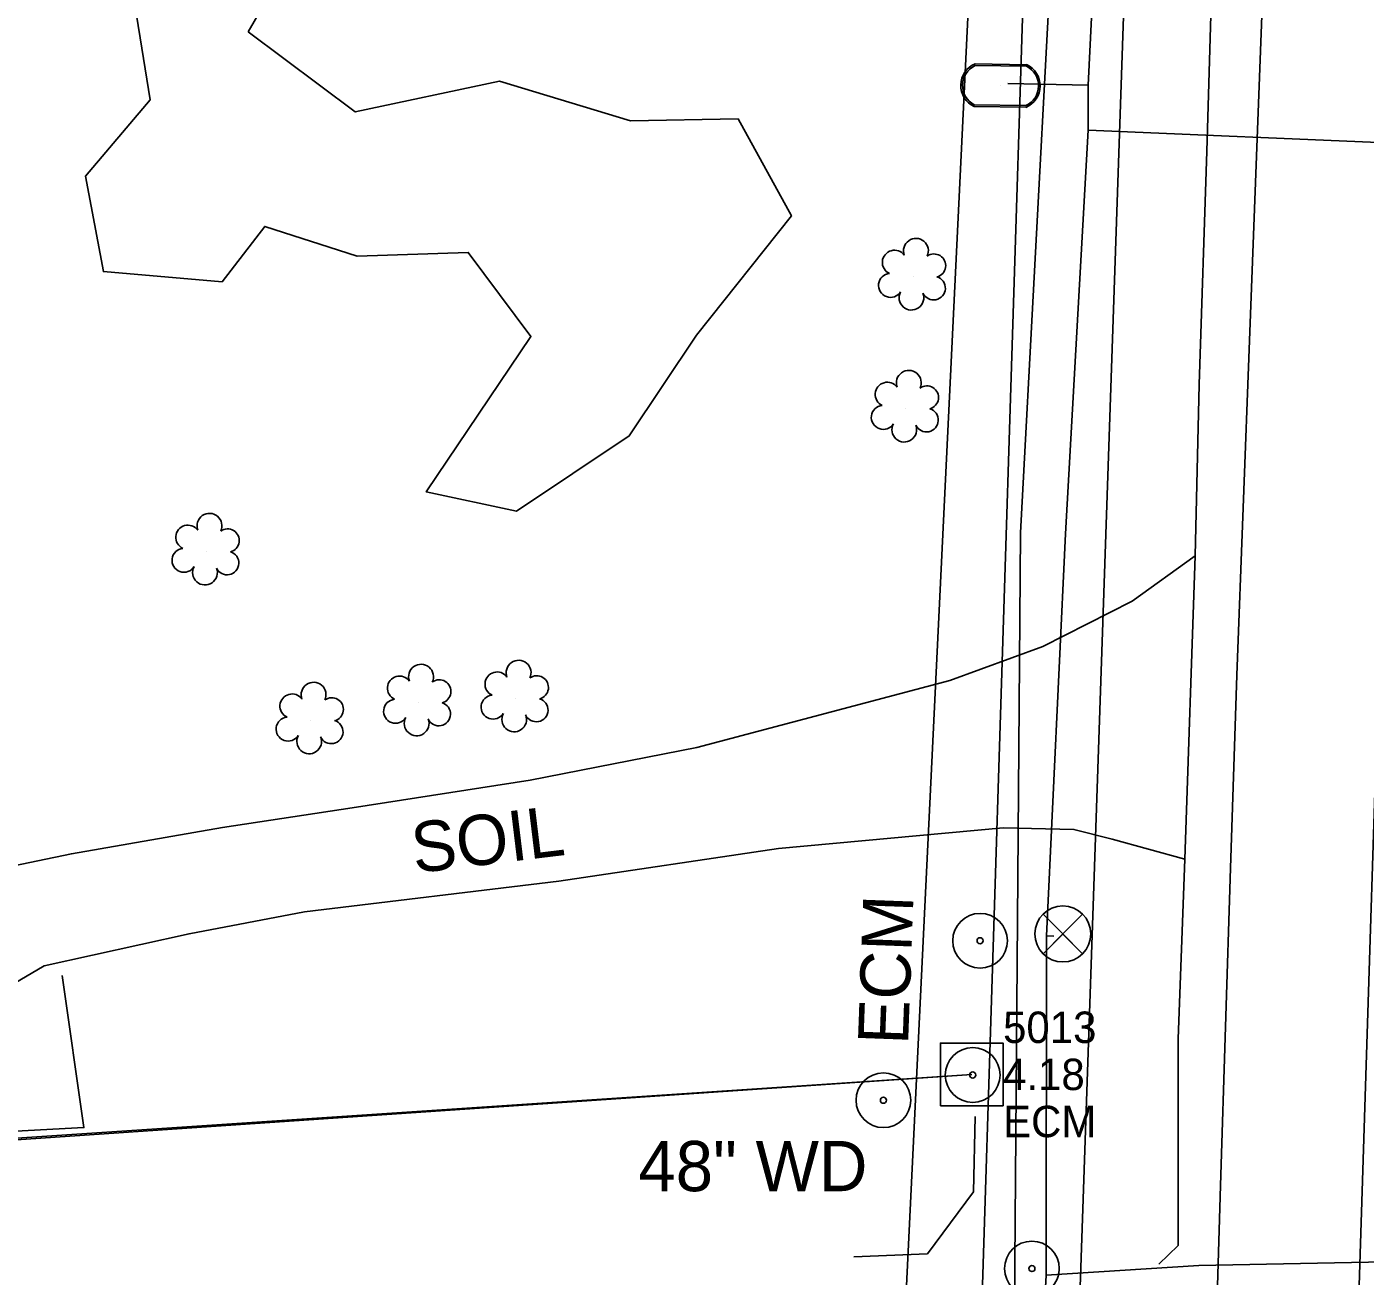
# Model space of a CAD drawing. Extents: x 3040896 to 3051146, y 687568 to 732976.
# Drawn here: x 3049720.6 to 3049827.2, y 689562.2 to 689661.6 of the extents above; entities that cross this region are included whole.
import ezdxf

# ---------------------------------------------------------------- set-up
doc = ezdxf.new("R2010")
doc.units = 0
for name, color, linetype in [('Exist Horizontal Alignment', 7, 'Continuous'), ('Exist Other Culture Fence Line', 7, 'Continuous'), ('Exist Other Culture Fence Line Text', 7, 'Continuous'), ('Exist Other Culture Located Object CELL', 7, 'Continuous'), ('Exist Property Line', 7, 'Continuous'), ('Exist Property Monument CELL', 7, 'Continuous'), ('Exist Property Monument Cogo Comment', 7, 'Continuous'), ('Exist Property Monument Cogo Elevation', 7, 'Continuous'), ('Exist Property Monument Cogo Number', 7, 'Continuous'), ('Exist Property Monument Text', 7, 'Continuous'), ('Exist Right of Way Line', 7, 'Continuous'), ('Exist Roads Change in Surface', 7, 'Continuous'), ('Exist Roads EOP', 7, 'Continuous'), ('Exist Roads EOT', 7, 'Continuous'), ('Exist Roads Soil', 7, 'Continuous'), ('Exist Roads Soil Text', 7, 'Continuous'), ('Exist Utilities Telephone UG Cable', 7, 'Continuous'), ('Exist Utilities Water Meter CELL', 7, 'Continuous'), ('Exist Utilities Water UG Line SUE', 7, 'Continuous'), ('Exist Utilities Water Valve CELL', 7, 'Continuous'), ('Exist Vegetation Shrub CELL', 7, 'Continuous'), ('Exist Vegetation Woods Line', 7, 'Continuous')]:
    doc.layers.add(name, color=color, linetype=linetype)

# ---------------------------------------------------------------- blocks, each defined once
blk = doc.blocks.new('EXIST PROPERTY MONUMENT')
at = {"layer": 'Exist Property Monument CELL'}
blk.add_line((0, 0), (0, 0), dxfattribs=at)
blk.add_lwpolyline([(-0.0499, -0.0499), (-0.0499, 0.0499), (0.0499, 0.0499), (0.0499, -0.0499), (-0.0499, -0.0499)], dxfattribs=at)

msp = doc.modelspace()

# ---------------------------------------------------------------- linework, layer by layer
at = {"layer": 'Exist Horizontal Alignment'}
msp.add_line((3049785.41, 688254.93), (3049834.01, 689792.8), dxfattribs=at)
at = {"layer": 'Exist Other Culture Fence Line'}
for points in [[(3049582.92, 689564.71), (3049601.65, 689565.87), (3049623.47, 689567.16), (3049676.08, 689570.13), (3049702.95, 689572.81), (3049725.11, 689574), (3049723.38, 689586.11)], [(3049796.1, 689574.87), (3049795.98, 689568.88), (3049792.31, 689563.95), (3049786.43, 689563.71)]]:
    msp.add_lwpolyline(points, dxfattribs=at)
at = {"layer": 'Exist Other Culture Located Object CELL'}
for centre, radius in [((3049796.5, 689588.87), 2.18), ((3049796.5, 689588.87), 0.24), ((3049795.91, 689578.18), 2.18), ((3049788.8, 689576.17), 2.18), ((3049795.91, 689578.18), 0.24), ((3049788.8, 689576.17), 0.24), ((3049800.63, 689562.77), 2.18), ((3049800.63, 689562.77), 0.24)]:
    msp.add_circle(centre, radius, dxfattribs=at)
at = {"layer": 'Exist Property Line'}
for q in [(3049573.92, 689563.44), (3049575.85, 689563.17)]:
    msp.add_line((3049795.83, 689578.23), q, dxfattribs=at)
at = {"layer": 'Exist Right of Way Line'}
for p, q in [((3049786.67, 689244.59), (3049805.44, 689838.5)), ((3049795.83, 689578.23), (3049795.83, 689578.23))]:
    msp.add_line(p, q, dxfattribs=at)
at = {"layer": 'Exist Roads Change in Surface'}
msp.add_lwpolyline([(3049810.75, 689563.13), (3049812.29, 689564.6)], dxfattribs=at)
at = {"layer": 'Exist Roads EOP'}
msp.add_lwpolyline([(3049812.29, 689564.6), (3049812.27, 689581.07), (3049812.81, 689595.36), (3049813.63, 689619.52), (3049813.95, 689633.16), (3049814.55, 689651.73), (3049815.1, 689669.79)], dxfattribs=at)
at = {"layer": 'Exist Roads EOT'}
msp.add_lwpolyline([(3049805.99, 689250.81), (3049806.64, 689272.48), (3049807.3, 689295.71), (3049808, 689316.09), (3049808.68, 689339.03), (3049809.45, 689362.67), (3049810.03, 689382.86), (3049810.78, 689407.09), (3049811.52, 689429.71), (3049812.19, 689453.36), (3049812.88, 689477.14), (3049813.4, 689494.33), (3049813.82, 689510.53), (3049814.46, 689531.2), (3049815.11, 689551.64), (3049815.66, 689569.39), (3049816.45, 689594.66), (3049816.94, 689610.02), (3049817.95, 689636.67), (3049818.91, 689661.83), (3049819.55, 689679.38), (3049820.14, 689701.33), (3049821.17, 689730.04), (3049822.31, 689760.81)], dxfattribs=at)
at = {"layer": 'Exist Roads Soil'}
for points in [[(3049813.63, 689619.52), (3049808.61, 689615.9), (3049801.5, 689612.3), (3049794.08, 689609.6), (3049773.93, 689604.26), (3049760.65, 689601.66), (3049746.48, 689599.45), (3049736.16, 689597.89), (3049724.12, 689595.79), (3049710.68, 689593.01), (3049704, 689592.12), (3049701.39, 689592.47), (3049697.08, 689593.97), (3049694.22, 689595.98), (3049691.13, 689603.39), (3049687.68, 689613.76)], [(3049678.6, 689613.2), (3049679.46, 689604.34), (3049681.63, 689596.84), (3049685.26, 689590.98), (3049690.79, 689585.86), (3049698.21, 689582.49), (3049707.31, 689581.46), (3049716.25, 689583.53), (3049721.96, 689586.88), (3049733.49, 689589.42), (3049742.69, 689591.17), (3049762.94, 689593.62), (3049780.43, 689596.22), (3049798.35, 689597.85), (3049803.97, 689597.73), (3049807.01, 689596.95), (3049812.81, 689595.36)]]:
    msp.add_lwpolyline(points, dxfattribs=at)
at = {"layer": 'Exist Utilities Telephone UG Cable'}
for points in [[(3049762.51, 688683.61), (3049763.35, 688783.45), (3049763.39, 688809.32), (3049768.46, 688891.44), (3049775.96, 689033.7), (3049761.48, 689036.51), (3049775.54, 689035.39), (3049777.18, 689233.45), (3049785.21, 689449.13), (3049795.62, 689664.26), (3049799.14, 689676.27)], [(3049771.96, 688683.24), (3049774.83, 688836.68), (3049786.32, 689061.63), (3049799.48, 689414.29), (3049808.2, 689670.95), (3049799.27, 689676.36)]]:
    msp.add_lwpolyline(points, dxfattribs=at)
at = {"layer": 'Exist Utilities Water Meter CELL'}
msp.add_line((3049798.12, 689656.96), (3049798.12, 689656.96), dxfattribs=at)
for points in [[(3049796.11, 689658.69), (3049800.19, 689658.62)], [(3049796.11, 689658.55), (3049800.19, 689658.49)], [(3049800.13, 689655.23), (3049796.03, 689655.29)], [(3049800.14, 689655.36), (3049796.04, 689655.43)]]:
    msp.add_lwpolyline(points, dxfattribs=at)
for centre, radius, start, end in [((3049796.82, 689656.97), 1.86, 112.2454, 245.0468), ((3049796.83, 689656.97), 1.73, 114.3683, 242.8497), ((3049799.42, 689656.94), 1.86, 292.7157, 65.3757), ((3049799.43, 689656.94), 1.73, 294.1945, 63.9402)]:
    msp.add_arc(centre, radius, start, end, dxfattribs=at)
at = {"layer": 'Exist Utilities Water UG Line SUE'}
for points in [[(3049763.98, 688683.56), (3049764.01, 688692.82), (3049764.93, 688765.77), (3049765.04, 688800.67), (3049768.97, 688869.09), (3049775.01, 688980.05), (3049777.74, 689033.76), (3049778.76, 689104.08), (3049780.89, 689206.11), (3049783.33, 689262.84), (3049786.04, 689305.13), (3049790.05, 689359.35), (3049791, 689437.72), (3049799.1, 689543.5), (3049799.71, 689621.35), (3049805.02, 689720.3), (3049804.55, 689756.69), (3049809.85, 689852.93), (3049811.63, 689887.74)], [(3049798.72, 689657.11), (3049805.12, 689657), (3049806.12, 689677.49)], [(3049805.12, 689657), (3049805.12, 689653.4), (3049830.08, 689652.34), (3049861.24, 689651.98)], [(3049805.12, 689653.4), (3049803.3, 689621.28), (3049801.78, 689589.26), (3049802.37, 689589.23)], [(3049801.78, 689589.26), (3049801.75, 689562.24), (3049813.92, 689563.01), (3049855.8, 689563.84)], [(3049795.6, 689449.32), (3049801.75, 689562.24)]]:
    msp.add_lwpolyline(points, dxfattribs=at)
at = {"layer": 'Exist Utilities Water Valve CELL'}
msp.add_lwpolyline([(3049804.67, 689590.99), (3049801.52, 689587.84), (3049803.09, 689589.41), (3049804.67, 689587.84), (3049801.52, 689590.99)], dxfattribs=at)
msp.add_circle((3049803.09, 689589.41), 2.23, dxfattribs=at)
at = {"layer": 'Exist Vegetation Shrub CELL'}
for p, q in [((3049791.16, 689641.76), (3049791.16, 689641.76)), ((3049790.59, 689631.25), (3049790.59, 689631.25)), ((3049734.89, 689619.86), (3049734.89, 689619.86)), ((3049751.74, 689607.85), (3049751.74, 689607.85)), ((3049759.52, 689608.17), (3049759.52, 689608.17)), ((3049743.18, 689606.42), (3049743.18, 689606.42))]:
    msp.add_line(p, q, dxfattribs=at)
for centre, radius, start, end in [((3049791.39, 689643.8), 0.99, 334.8391, 200.4717), ((3049789.68, 689642.88), 0.968, 35.8908, 245.4216), ((3049792.83, 689642.62), 0.929, 284.4567, 126.0861), ((3049789.36, 689641.05), 0.955, 95.1099, 327.9534), ((3049792.8, 689640.83), 0.937, 204.9913, 73.4601), ((3049791.03, 689640.07), 0.984, 151.2797, 21.387), ((3049790.82, 689633.29), 0.99, 334.8391, 200.4717), ((3049789.11, 689632.37), 0.968, 35.8908, 245.4216), ((3049792.26, 689632.12), 0.929, 284.4567, 126.0861), ((3049788.79, 689630.54), 0.955, 95.1099, 327.9534), ((3049792.23, 689630.32), 0.937, 204.9913, 73.4601), ((3049790.46, 689629.56), 0.984, 151.2797, 21.387), ((3049735.12, 689621.91), 0.99, 334.8391, 200.4717), ((3049733.4, 689620.99), 0.968, 35.8908, 245.4216), ((3049736.56, 689620.73), 0.929, 284.4567, 126.0861), ((3049733.09, 689619.16), 0.955, 95.1099, 327.9534), ((3049736.52, 689618.94), 0.937, 204.9913, 73.4601), ((3049734.76, 689618.18), 0.984, 151.2797, 21.387), ((3049751.97, 689609.89), 0.99, 334.8391, 200.4717), ((3049759.74, 689610.21), 0.99, 334.8391, 200.4717), ((3049743.41, 689608.46), 0.99, 334.8391, 200.4717), ((3049750.26, 689608.98), 0.968, 35.8908, 245.4216), ((3049753.42, 689608.72), 0.929, 284.4567, 126.0861), ((3049758.03, 689609.3), 0.968, 35.8908, 245.4216), ((3049761.19, 689609.04), 0.929, 284.4567, 126.0861), ((3049741.7, 689607.55), 0.968, 35.8908, 245.4216), ((3049757.71, 689607.47), 0.955, 95.1099, 327.9534), ((3049744.86, 689607.29), 0.929, 284.4567, 126.0861), ((3049749.94, 689607.14), 0.955, 95.1099, 327.9534), ((3049753.38, 689606.92), 0.937, 204.9913, 73.4601), ((3049761.15, 689607.24), 0.937, 204.9913, 73.4601), ((3049741.38, 689605.72), 0.955, 95.1099, 327.9534), ((3049744.82, 689605.5), 0.937, 204.9913, 73.4601), ((3049751.62, 689606.17), 0.984, 151.2797, 21.387), ((3049759.39, 689606.49), 0.984, 151.2797, 21.387), ((3049743.06, 689604.74), 0.984, 151.2797, 21.387)]:
    msp.add_arc(centre, radius, start, end, dxfattribs=at)
at = {"layer": 'Exist Vegetation Woods Line'}
for points in [[(3049741.64, 689667.2), (3049738.2, 689661.23)], [(3049738.2, 689661.23), (3049746.73, 689654.86), (3049758.22, 689657.3), (3049768.65, 689654.16), (3049777.22, 689654.32), (3049781.47, 689646.59), (3049773.91, 689637.09), (3049768.56, 689629.07), (3049759.58, 689623.07), (3049752.39, 689624.61), (3049760.72, 689636.97), (3049755.73, 689643.68), (3049746.88, 689643.37), (3049739.52, 689645.75), (3049736.12, 689641.32), (3049726.67, 689642.15), (3049725.24, 689649.75), (3049730.38, 689655.82), (3049728.64, 689666.71)]]:
    msp.add_lwpolyline(points, dxfattribs=at)

# ---------------------------------------------------------------- block references
at = {"layer": 'Exist Property Monument CELL', "xscale": 50, "yscale": 50}
msp.add_blockref('EXIST PROPERTY MONUMENT', (3049795.83, 689578.23), dxfattribs=at)
msp.add_blockref('EXIST PROPERTY MONUMENT', (3049795.83, 689578.23), dxfattribs=at)

# ---------------------------------------------------------------- texts
at = {"layer": 'Exist Other Culture Fence Line Text'}
msp.add_text('48" WD', height=4, dxfattribs=at).set_placement((3049769.28, 689568.93))
at = {"layer": 'Exist Property Monument Cogo Comment'}
msp.add_text('ECM', height=2.5, dxfattribs=at).set_placement((3049798.33, 689573.23))
msp.add_text('ECM', height=2.5, dxfattribs=at).set_placement((3049798.33, 689573.23))
at = {"layer": 'Exist Property Monument Cogo Elevation'}
msp.add_text('4.18', height=2.5, dxfattribs=at).set_placement((3049798.33, 689576.98))
msp.add_text('4.18', height=2.5, dxfattribs=at).set_placement((3049798.33, 689576.98))
at = {"layer": 'Exist Property Monument Cogo Number'}
msp.add_text('5013', height=2.5, dxfattribs=at).set_placement((3049798.33, 689580.73))
msp.add_text('5013', height=2.5, dxfattribs=at).set_placement((3049798.33, 689580.73))
at = {"layer": 'Exist Property Monument Text'}
msp.add_text('ECM', height=4, rotation=87.8991, dxfattribs=at).set_placement((3049790.76, 689580.55))
at = {"layer": 'Exist Roads Soil Text'}
msp.add_text('SOIL', height=4, rotation=6.915, dxfattribs=at).set_placement((3049751.46, 689594.24))

doc.saveas('drawing.dxf')
